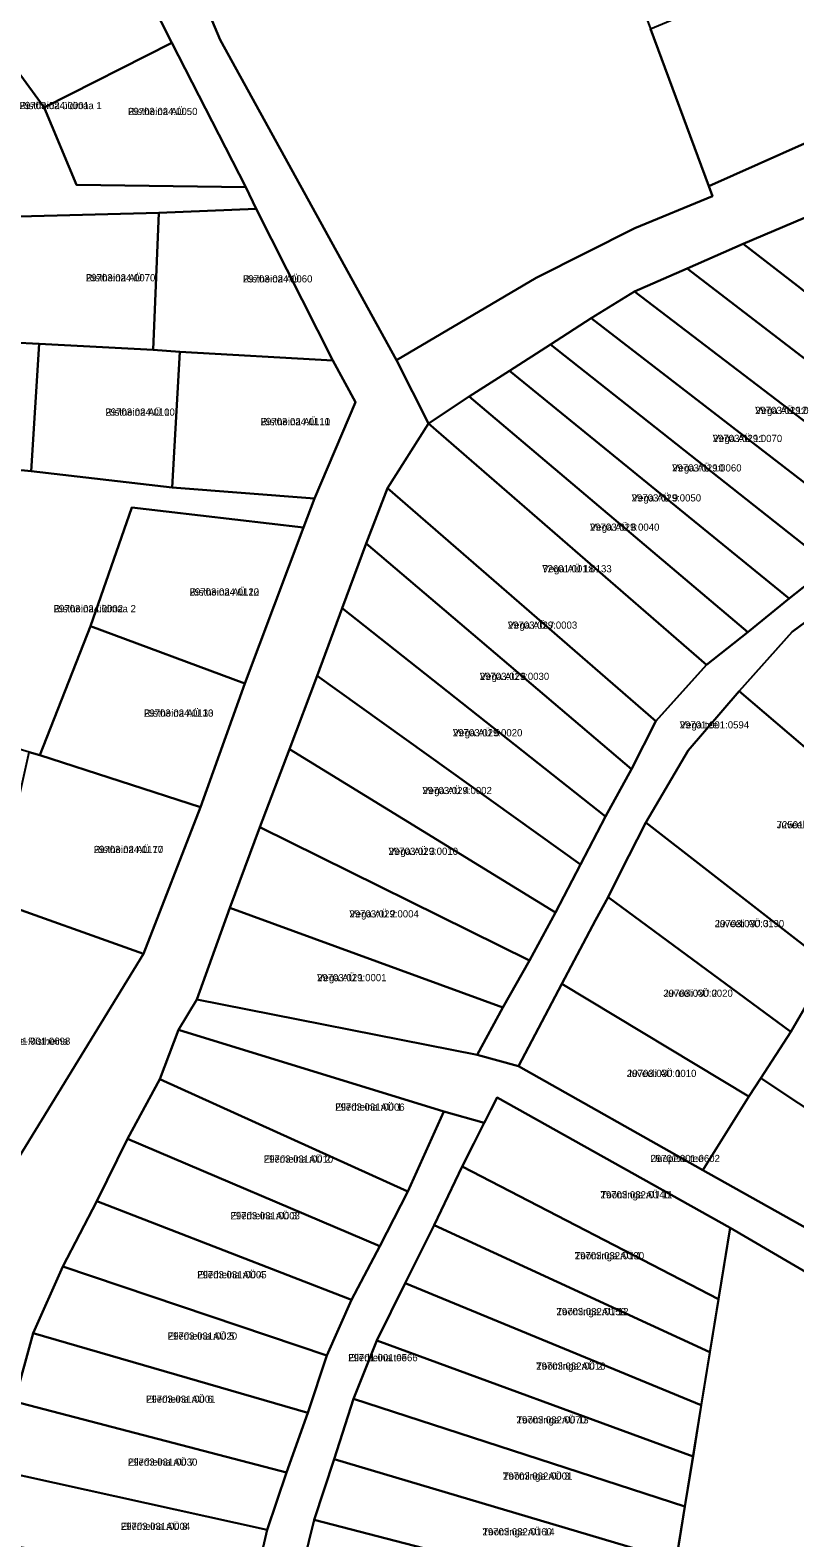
# Model space of a CAD drawing. Extents: x 504287 to 537970, y 6539941 to 6586214.
# Drawn here: x 518425.8 to 518585.5, y 6560795.2 to 6561110.1 of the extents above; entities that cross this region are included whole.
import ezdxf

# ---------------------------------------------------------------- set-up
doc = ezdxf.new("R2010")
doc.units = 0
for name, color, linetype in [('L_AADRESS', 7, 'Continuous'), ('PIIR', 7, 'Continuous'), ('TUNNUS', 7, 'Continuous')]:
    doc.layers.add(name, color=color, linetype=linetype)

msp = doc.modelspace()

# ---------------------------------------------------------------- linework, layer by layer
at = {"layer": 'PIIR'}
for points in [[(518367.07, 6560719.08), (518370.03, 6560803.08), (518389.88, 6560820.02), (518449.53, 6560917.15), (518461.42, 6560947.82), (518470.68, 6560973.62), (518482.91, 6561006.2), (518485.23, 6561012.25), (518493.76, 6561032.39), (518489.05, 6561041.1), (518473.01, 6561072.73), (518470.86, 6561077.26), (518455.39, 6561107.44), (518441.85, 6561134.23), (518429.34, 6561158.7), (518405, 6561224.35), (518399.83, 6561238.56), (518392.11, 6561259.42), (518384.68, 6561279.75), (518377.32, 6561299.82), (518370.28, 6561319.65), (518362.78, 6561339.16), (518355.48, 6561358.99), (518347.39, 6561380.81)], [(518436.08, 6561178.02), (518465.5, 6561108.05), (518502.31, 6561041.16), (518509.02, 6561027.95), (518500.47, 6561014.45), (518495.97, 6561002.88), (518490.99, 6560989.4), (518485.79, 6560975.26), (518480.01, 6560959.92), (518473.78, 6560943.6), (518467.54, 6560926.82), (518460.61, 6560907.64), (518456.81, 6560901.28), (518452.93, 6560890.98), (518446.13, 6560878.53), (518439.78, 6560865.55), (518432.68, 6560851.9), (518426.46, 6560837.98), (518422.54, 6560823.69), (518418.27, 6560809.48), (518413.67, 6560795.15)], [(518684.29, 6561113.19), (518654.45, 6561101.81), (518654.21, 6561099.18), (518624.04, 6561086.68), (518615.82, 6561082.94), (518601.19, 6561076.84), (518587.53, 6561070.89), (518574.73, 6561065.44), (518563.01, 6561060.29), (518552.02, 6561055.47), (518542.96, 6561049.92), (518534.48, 6561044.43), (518525.95, 6561038.91), (518517.48, 6561033.57), (518509.02, 6561027.95), (518502.31, 6561041.16), (518531.53, 6561058.34), (518552.07, 6561068.72), (518568.31, 6561075.44), (518567.55, 6561077.49), (518628.15, 6561104.5), (518648.58, 6561113.51)], [(518587.89, 6560986.61), (518584.97, 6560984.42), (518573.88, 6560972.01), (518563.22, 6560959.63), (518554.41, 6560944.62), (518549.05, 6560934.07), (518546.54, 6560929.03), (518543.89, 6560924.24), (518536.89, 6560910.93), (518527.81, 6560893.71), (518519.18, 6560896.11), (518524.56, 6560905.96), (518530.09, 6560915.78), (518535.52, 6560925.83), (518540.74, 6560935.83), (518545.98, 6560945.88), (518551.4, 6560955.72), (518556.51, 6560965.75), (518567.08, 6560977.51), (518575.69, 6560984.38), (518584.36, 6560991.39), (518592.93, 6560998.21)], [(518472.43, 6560784.26), (518475.3, 6560796.89), (518479.38, 6560808.88), (518483.79, 6560821.32), (518487.78, 6560833.28), (518492.93, 6560844.94), (518498.85, 6560856.16), (518504.67, 6560867.57), (518512.21, 6560884.25), (518520.63, 6560881.86), (518516.05, 6560872.78), (518510.21, 6560860.49), (518504.12, 6560848.44), (518498.26, 6560836.46), (518493.36, 6560824.28), (518489.3, 6560811.68), (518485.13, 6560799.01), (518481.85, 6560785.72)]]:
    msp.add_lwpolyline(points, dxfattribs=at)
for points in [[(518421.86, 6561266.67), (518437.17, 6561260.95), (518461.68, 6561247.1), (518473.29, 6561237.43), (518488.32, 6561225), (518502.62, 6561213.26), (518514.73, 6561202.9), (518521.8, 6561188.31), (518528.99, 6561173.79), (518535.86, 6561158.97), (518542.87, 6561144.39), (518549.48, 6561126.35), (518555.38, 6561110.32), (518567.55, 6561077.49), (518568.31, 6561075.44), (518552.07, 6561068.72), (518531.53, 6561058.34), (518502.31, 6561041.16), (518465.5, 6561108.05), (518436.08, 6561178.02), (518408.13, 6561262.48), (518416.34, 6561267.95), (518421.96, 6561277.24)], [(518555.38, 6561110.32), (518576.72, 6561119.3), (518610.61, 6561138.52), (518628.15, 6561104.5), (518567.55, 6561077.49)], [(518423.12, 6561101.66), (518418.46, 6561115.99), (518441.85, 6561134.23), (518455.39, 6561107.44), (518428.77, 6561093.92)], [(518415.12, 6561115.6), (518418.46, 6561115.99), (518423.12, 6561101.66), (518428.77, 6561093.92), (518435.51, 6561077.76), (518470.86, 6561077.26), (518473.01, 6561072.73), (518452.72, 6561071.95), (518423.5, 6561071.17), (518418.19, 6561071.35), (518418.35, 6561101.35), (518412.07, 6561114.72)], [(518428.77, 6561093.92), (518455.39, 6561107.44), (518470.86, 6561077.26), (518435.51, 6561077.76)], [(518422.18, 6561044.87), (518423.5, 6561071.17), (518452.72, 6561071.95), (518451.5, 6561043.3), (518427.72, 6561044.55)], [(518451.5, 6561043.3), (518452.72, 6561071.95), (518473.01, 6561072.73), (518489.05, 6561041.1), (518457.06, 6561042.91)], [(518598.79, 6561046.66), (518590.98, 6561052.81), (518586.1, 6561056.71), (518574.73, 6561065.44), (518587.53, 6561070.89), (518640.36, 6561026.1), (518630.14, 6561021.59), (518607.37, 6561039.96)], [(518574.73, 6561065.44), (518586.1, 6561056.71), (518590.98, 6561052.81), (518598.79, 6561046.66), (518607.37, 6561039.96), (518630.14, 6561021.59), (518620.79, 6561015.98), (518563.01, 6561060.29)], [(518563.01, 6561060.29), (518620.79, 6561015.98), (518611.37, 6561010.28), (518552.02, 6561055.47)], [(518552.02, 6561055.47), (518611.37, 6561010.28), (518602.04, 6561004.38), (518542.96, 6561049.92)], [(518542.96, 6561049.92), (518602.04, 6561004.38), (518592.93, 6560998.21), (518534.48, 6561044.43)], [(518391.03, 6561046.41), (518422.18, 6561044.87), (518427.72, 6561044.55), (518426.04, 6561017.97), (518422.49, 6561018.34), (518392.38, 6561021.45)], [(518427.72, 6561044.55), (518451.5, 6561043.3), (518457.06, 6561042.91), (518455.48, 6561014.59), (518426.04, 6561017.97)], [(518457.06, 6561042.91), (518489.05, 6561041.1), (518493.76, 6561032.39), (518485.23, 6561012.25), (518455.48, 6561014.59)], [(518534.48, 6561044.43), (518592.93, 6560998.21), (518584.36, 6560991.39), (518525.95, 6561038.91)], [(518525.95, 6561038.91), (518584.36, 6560991.39), (518575.69, 6560984.38), (518517.48, 6561033.57)], [(518567.08, 6560977.51), (518509.02, 6561027.95), (518517.48, 6561033.57), (518575.69, 6560984.38)], [(518509.02, 6561027.95), (518567.08, 6560977.51), (518556.51, 6560965.75), (518500.47, 6561014.45)], [(518426.04, 6561017.97), (518455.48, 6561014.59), (518485.23, 6561012.25), (518482.91, 6561006.2), (518447.04, 6561010.4), (518438.46, 6560985.6), (518427.82, 6560958.68), (518425.62, 6560959.31), (518422.62, 6560960.21), (518421.99, 6560989.81), (518422.49, 6561018.34)], [(518495.97, 6561002.88), (518500.47, 6561014.45), (518556.51, 6560965.75), (518551.4, 6560955.72)], [(518447.04, 6561010.4), (518482.91, 6561006.2), (518470.68, 6560973.62), (518438.46, 6560985.6)], [(518495.97, 6561002.88), (518551.4, 6560955.72), (518545.98, 6560945.88), (518490.99, 6560989.4)], [(518490.99, 6560989.4), (518545.98, 6560945.88), (518540.74, 6560935.83), (518485.79, 6560975.26)], [(518438.46, 6560985.6), (518470.68, 6560973.62), (518461.42, 6560947.82), (518427.82, 6560958.68)], [(518584.97, 6560984.42), (518587.89, 6560986.61), (518625.69, 6560951.62), (518610.43, 6560940.82), (518573.88, 6560972.01)], [(518540.74, 6560935.83), (518535.52, 6560925.83), (518480.01, 6560959.92), (518485.79, 6560975.26)], [(518563.22, 6560959.63), (518573.88, 6560972.01), (518610.43, 6560940.82), (518611.82, 6560939.65), (518602.34, 6560928.39), (518592.83, 6560914.74), (518554.41, 6560944.62)], [(518480.01, 6560959.92), (518535.52, 6560925.83), (518530.09, 6560915.78), (518473.78, 6560943.6)], [(518427.82, 6560958.68), (518461.42, 6560947.82), (518449.53, 6560917.15), (518417.06, 6560928.74), (518421.58, 6560941.13), (518425.62, 6560959.31)], [(518549.05, 6560934.07), (518554.41, 6560944.62), (518592.83, 6560914.74), (518590.46, 6560910.82), (518584.65, 6560900.87), (518546.54, 6560929.03)], [(518473.78, 6560943.6), (518530.09, 6560915.78), (518524.56, 6560905.96), (518467.54, 6560926.82)], [(518391.7, 6560937.64), (518417.06, 6560928.74), (518449.53, 6560917.15), (518389.88, 6560820.02)], [(518543.89, 6560924.24), (518546.54, 6560929.03), (518584.65, 6560900.87), (518578.45, 6560891.2), (518575.89, 6560887.39), (518536.89, 6560910.93)], [(518524.56, 6560905.96), (518519.18, 6560896.11), (518460.61, 6560907.64), (518467.54, 6560926.82)], [(518536.89, 6560910.93), (518575.89, 6560887.39), (518566.29, 6560872.01), (518527.81, 6560893.71)], [(518590.46, 6560910.82), (518623.96, 6560886.45), (518610.06, 6560870.18), (518578.45, 6560891.2), (518584.65, 6560900.87)], [(518456.81, 6560901.28), (518460.61, 6560907.64), (518519.18, 6560896.11), (518527.81, 6560893.71), (518566.29, 6560872.01), (518596.98, 6560854.84), (518601.69, 6560852.23), (518616.54, 6560839.9), (518606.54, 6560839.76), (518572.01, 6560859.95), (518523.33, 6560887.21), (518520.63, 6560881.86), (518512.21, 6560884.25)], [(518456.81, 6560901.28), (518512.21, 6560884.25), (518504.67, 6560867.57), (518452.93, 6560890.98)], [(518452.93, 6560890.98), (518504.67, 6560867.57), (518498.85, 6560856.16), (518446.13, 6560878.53)], [(518575.89, 6560887.39), (518578.45, 6560891.2), (518610.06, 6560870.18), (518596.98, 6560854.84), (518566.29, 6560872.01)], [(518523.33, 6560887.21), (518572.01, 6560859.95), (518569.58, 6560845.04), (518516.05, 6560872.78)], [(518446.13, 6560878.53), (518498.85, 6560856.16), (518492.93, 6560844.94), (518439.78, 6560865.55)], [(518516.05, 6560872.78), (518569.58, 6560845.04), (518567.79, 6560834.01), (518510.21, 6560860.49)], [(518439.78, 6560865.55), (518492.93, 6560844.94), (518487.78, 6560833.28), (518432.68, 6560851.9)], [(518510.21, 6560860.49), (518567.79, 6560834.01), (518565.99, 6560822.95), (518504.12, 6560848.44)], [(518768.89, 6560651.51), (518738.83, 6560735.38), (518652.65, 6560733.81), (518629.3, 6560780.95), (518581.89, 6560787.89), (518576.36, 6560731.36), (518567.4, 6560635.25), (518535.13, 6560633.13), (518572.01, 6560859.95), (518606.54, 6560839.76), (518616.54, 6560839.9), (518648.28, 6560813.79), (518647.42, 6560811.44), (518652.72, 6560810.4), (518899.74, 6560747.79), (518890.66, 6560660.58), (518836.98, 6560656.24)], [(518432.68, 6560851.9), (518487.78, 6560833.28), (518483.79, 6560821.32), (518426.46, 6560837.98)], [(518504.12, 6560848.44), (518565.99, 6560822.95), (518564.25, 6560812.24), (518498.26, 6560836.46)], [(518426.46, 6560837.98), (518483.79, 6560821.32), (518479.38, 6560808.88), (518422.54, 6560823.69)], [(518498.26, 6560836.46), (518564.25, 6560812.24), (518562.54, 6560801.75), (518493.36, 6560824.28)], [(518422.54, 6560823.69), (518479.38, 6560808.88), (518475.3, 6560796.89), (518418.27, 6560809.48)], [(518493.36, 6560824.28), (518562.54, 6560801.75), (518560.71, 6560790.45), (518489.3, 6560811.68)], [(518418.27, 6560809.48), (518475.29, 6560796.89), (518472.42, 6560784.26), (518413.67, 6560795.15)], [(518489.3, 6560811.68), (518560.71, 6560790.45), (518558.98, 6560779.81), (518485.13, 6560799.01)], [(518485.13, 6560799.01), (518558.98, 6560779.81), (518557.25, 6560769.15), (518481.85, 6560785.72)]]:
    msp.add_lwpolyline(points, close=True, dxfattribs=at)

# ---------------------------------------------------------------- texts
at = {"layer": 'L_AADRESS'}
for s, p in [('Ristheina üldmaa 1', (518423.61, 6561093.58)), ('Ristheina AÜ 5', (518446.27, 6561092.35)), ('Ristheina AÜ 7', (518437.47, 6561057.62)), ('Ristheina AÜ 6', (518470.27, 6561057.39)), ('Ristheina AÜ 10', (518441.54, 6561029.57)), ('Ristheina AÜ 11', (518473.96, 6561027.58)), ('Vega AÜ 12', (518577.23, 6561029.92)), ('Vega AÜ 11', (518568.37, 6561024.07)), ('Vega AÜ 10', (518559.89, 6561017.91)), ('Vega AÜ 9', (518551.44, 6561011.65)), ('Vega AÜ 8', (518542.73, 6561005.54)), ('Vega AÜ 18', (518532.77, 6560996.85)), ('Ristheina AÜ 12', (518459.13, 6560992.01)), ('Ristheina üldmaa 2', (518430.74, 6560988.51)), ('Vega AÜ 7', (518525.57, 6560985.08)), ('Vega AÜ 6', (518519.72, 6560974.38)), ('Ristheina AÜ 13', (518449.6, 6560966.71)), ('Vega AÜ 5', (518514.12, 6560962.61)), ('Vega tee', (518561.47, 6560964.25)), ('Vega AÜ 4', (518507.75, 6560950.54)), ('Juveeli AÜ 4', (518581.72, 6560943.38)), ('Ristheina AÜ 17', (518439.11, 6560938.23)), ('Vega AÜ 3', (518500.68, 6560937.85)), ('Vega AÜ 2', (518492.49, 6560924.78)), ('Juveeli AÜ 3', (518568.79, 6560922.75)), ('Vega AÜ 1', (518485.75, 6560911.46)), ('Juveeli AÜ 2', (518558.06, 6560908.21)), ('Väike-Ristheina', (518419.71, 6560898.19)), ('Juveeli AÜ 1', (518550.46, 6560891.47)), ('Ellerheina AÜ 1', (518489.53, 6560884.43)), ('Ellerheina AÜ 2', (518474.61, 6560873.57)), ('Uuepere tee', (518555.37, 6560873.7)), ('Toominga AÜ 11', (518544.94, 6560866.12)), ('Ellerheina AÜ 3', (518467.66, 6560861.74)), ('Toominga AÜ 1', (518539.55, 6560853.4)), ('Ellerheina AÜ 4', (518460.71, 6560849.42)), ('Toominga AÜ 12', (518535.73, 6560841.72)), ('Ellerheina AÜ 5', (518454.55, 6560836.61)), ('Ellerheina tee', (518492.25, 6560832.1)), ('Toominga AÜ 2', (518531.49, 6560830.34)), ('Ellerheina AÜ 6', (518450.03, 6560823.43)), ('Toominga AÜ 13', (518527.4, 6560819.11)), ('Ellerheina AÜ 7', (518446.24, 6560810.29)), ('Toominga AÜ 3', (518524.56, 6560807.37)), ('Ellerheina AÜ 8', (518444.75, 6560796.87)), ('Toominga AÜ 14', (518520.29, 6560795.74))]:
    msp.add_text(s, height=1.5, dxfattribs=at).set_placement(p)
at = {"layer": 'TUNNUS'}
for s, p in [('29703:024:0001', (518423.61, 6561093.58)), ('29703:024:0050', (518446.27, 6561092.35)), ('29703:024:0070', (518437.47, 6561057.62)), ('29703:024:0060', (518470.27, 6561057.39)), ('29703:024:0100', (518441.54, 6561029.57)), ('29703:024:0110', (518473.96, 6561027.58)), ('29703:029:0080', (518577.23, 6561029.92)), ('29703:029:0070', (518568.37, 6561024.07)), ('29703:029:0060', (518559.89, 6561017.91)), ('29703:029:0050', (518551.44, 6561011.65)), ('29703:029:0040', (518542.73, 6561005.54)), ('72601:001:0133', (518532.77, 6560996.85)), ('29703:024:0120', (518459.13, 6560992.01)), ('29703:024:0002', (518430.74, 6560988.51)), ('29703:029:0003', (518525.57, 6560985.08)), ('29703:029:0030', (518519.72, 6560974.38)), ('29703:024:0130', (518449.6, 6560966.71)), ('29703:029:0020', (518514.12, 6560962.61)), ('29701:001:0594', (518561.47, 6560964.25)), ('29703:029:0002', (518507.75, 6560950.54)), ('72501:001:0447', (518581.72, 6560943.38)), ('29703:024:0170', (518439.11, 6560938.23)), ('29703:029:0010', (518500.68, 6560937.85)), ('29703:029:0004', (518492.49, 6560924.78)), ('29703:030:0190', (518568.79, 6560922.75)), ('29703:029:0001', (518485.75, 6560911.46)), ('29703:030:0020', (518558.06, 6560908.21)), ('29701:001:0698', (518419.71, 6560898.19)), ('29703:030:0010', (518550.46, 6560891.47)), ('29703:031:0006', (518489.53, 6560884.43)), ('29703:031:0010', (518474.61, 6560873.57)), ('29701:001:0602', (518555.37, 6560873.7)), ('29703:032:0140', (518544.94, 6560866.12)), ('29703:031:0003', (518467.66, 6560861.74)), ('29703:032:0130', (518539.55, 6560853.4)), ('29703:031:0005', (518460.71, 6560849.42)), ('29703:032:0150', (518535.73, 6560841.72)), ('29703:031:0020', (518454.55, 6560836.61)), ('29701:001:0566', (518492.25, 6560832.1)), ('29703:032:0010', (518531.49, 6560830.34)), ('29703:031:0001', (518450.03, 6560823.43)), ('29703:032:0070', (518527.4, 6560819.11)), ('29703:031:0030', (518446.24, 6560810.29)), ('29703:032:0001', (518524.56, 6560807.37)), ('29703:031:0004', (518444.75, 6560796.87)), ('29703:032:0160', (518520.29, 6560795.74))]:
    msp.add_text(s, height=1.5, dxfattribs=at).set_placement(p)

doc.saveas('drawing.dxf')
